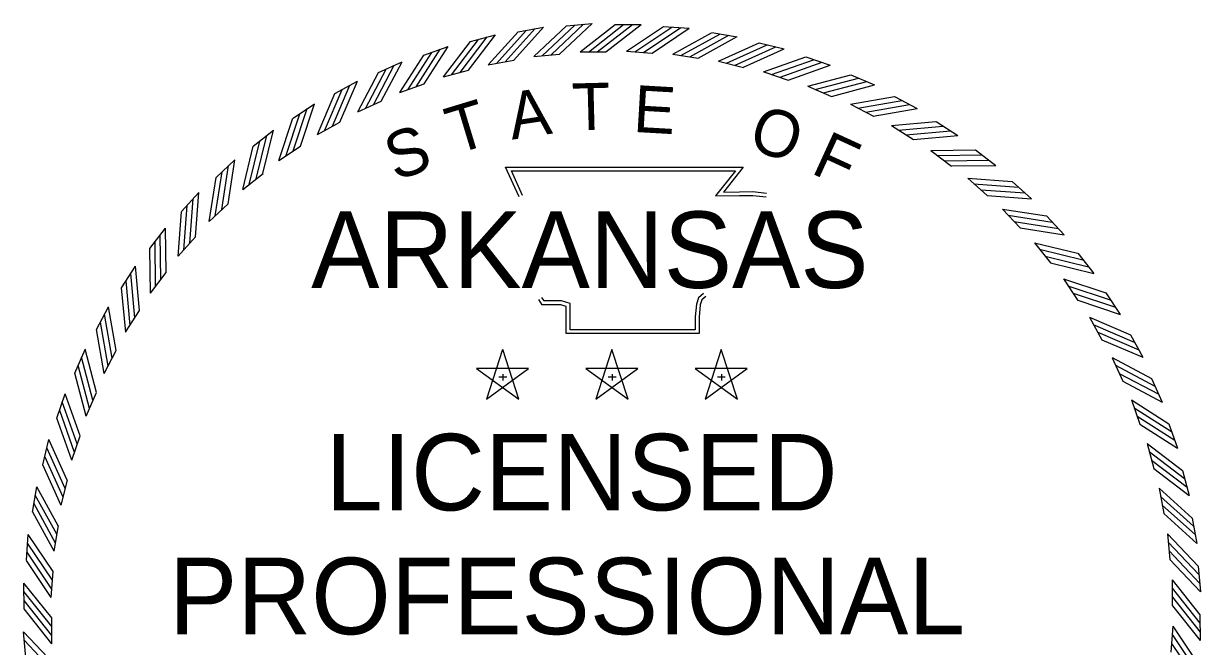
# Model space of a CAD drawing. Extents: x 1370130 to 1380143, y 377636 to 380256.
# Drawn here: x 1379550.7 to 1379757.3, y 377838.9 to 377948.2 of the extents above; entities that cross this region are included whole.
import ezdxf

# ---------------------------------------------------------------- set-up
doc = ezdxf.new("R2010")
doc.units = 0
doc.layers.add('STAMP_JUSTIN', color=7, linetype='Continuous')

msp = doc.modelspace()

# ---------------------------------------------------------------- linework, layer by layer
at = {"layer": 'STAMP_JUSTIN'}
for p, q in [((1379637.55, 377946.8), (1379642.01, 377947.59)), ((1379646.02, 377947.81), (1379650.53, 377948.23)), ((1379654.59, 377948.06), (1379659.11, 377948.06)), ((1379663.06, 377947.72), (1379667.57, 377947.39)), ((1379629.2, 377945.09), (1379633.57, 377946.24)), ((1379671.52, 377946.63), (1379675.99, 377945.92)), ((1379621.01, 377942.7), (1379625.28, 377944.21)), ((1379648.41, 377943.25), (1379652.95, 377943.25)), ((1379656.55, 377943.38), (1379661.07, 377943.04)), ((1379679.86, 377944.83), (1379684.25, 377943.76)), ((1379613.05, 377939.64), (1379617.18, 377941.5)), ((1379632.31, 377940.99), (1379636.78, 377941.77)), ((1379640.32, 377942.45), (1379644.83, 377942.87)), ((1379664.67, 377942.83), (1379669.15, 377942.13)), ((1379672.72, 377941.62), (1379677.12, 377940.54)), ((1379688.02, 377942.36), (1379692.31, 377940.93)), ((1379624.45, 377938.87), (1379628.84, 377940.02)), ((1379680.64, 377939.74), (1379684.94, 377938.31)), ((1379695.94, 377939.22), (1379700.1, 377937.44)), ((1379605.37, 377935.94), (1379609.33, 377938.13)), ((1379616.8, 377936.1), (1379621.07, 377937.62)), ((1379688.38, 377937.22), (1379692.54, 377935.44)), ((1379703.59, 377935.43), (1379707.58, 377933.32)), ((1379598.03, 377931.61), (1379601.79, 377934.12)), ((1379609.4, 377932.72), (1379613.53, 377934.58)), ((1379695.88, 377934.07), (1379699.89, 377931.95)), ((1379602.3, 377928.74), (1379606.27, 377930.93)), ((1379710.89, 377931.03), (1379714.7, 377928.59)), ((1379591.06, 377926.69), (1379594.6, 377929.5)), ((1379703.09, 377930.31), (1379706.91, 377927.86)), ((1379595.56, 377924.18), (1379599.33, 377926.69)), ((1379709.98, 377925.96), (1379713.58, 377923.21)), ((1379717.8, 377926.04), (1379721.4, 377923.3)), ((1379584.53, 377921.21), (1379587.83, 377924.3)), ((1379589.22, 377919.08), (1379592.77, 377921.9)), ((1379716.48, 377921.06), (1379719.84, 377918.02)), ((1379724.28, 377920.5), (1379727.64, 377917.46)), ((1379578.46, 377915.21), (1379581.5, 377918.57)), ((1379583.31, 377913.48), (1379586.62, 377916.58)), ((1379722.55, 377915.65), (1379725.65, 377912.34)), ((1379730.28, 377914.44), (1379733.38, 377911.14)), ((1379572.92, 377908.73), (1379575.67, 377912.33)), ((1379577.9, 377907.4), (1379580.94, 377910.77)), ((1379728.15, 377909.75), (1379730.97, 377906.19)), ((1379735.76, 377907.9), (1379738.57, 377904.36)), ((1379567.93, 377901.82), (1379570.37, 377905.63)), ((1379573, 377900.9), (1379575.75, 377904.51)), ((1379733.25, 377903.4), (1379735.77, 377899.63)), ((1379740.68, 377900.94), (1379743.19, 377897.17)), ((1379563.53, 377894.51), (1379565.64, 377898.51)), ((1379568.65, 377894.02), (1379571.1, 377897.84)), ((1379737.81, 377896.66), (1379740, 377892.69)), ((1379745.01, 377893.59), (1379747.2, 377889.63)), ((1379559.74, 377886.87), (1379561.52, 377891.03)), ((1379564.89, 377886.81), (1379567.01, 377890.81)), ((1379634.82, 377890.99), (1379631.99, 377882.3)), ((1379637.64, 377882.31), (1379634.83, 377891)), ((1379654.01, 377890.99), (1379651.18, 377882.3)), ((1379656.83, 377882.31), (1379654.01, 377891)), ((1379673.2, 377890.99), (1379670.37, 377882.3)), ((1379676.02, 377882.31), (1379673.2, 377891)), ((1379741.79, 377889.56), (1379743.65, 377885.43)), ((1379639.38, 377887.67), (1379630.25, 377887.68)), ((1379630.26, 377887.67), (1379637.64, 377882.3)), ((1379632, 377882.31), (1379639.39, 377887.67)), ((1379658.57, 377887.67), (1379649.44, 377887.68)), ((1379649.45, 377887.67), (1379656.83, 377882.3)), ((1379651.19, 377882.31), (1379658.58, 377887.67)), ((1379677.76, 377887.67), (1379668.63, 377887.68)), ((1379668.63, 377887.67), (1379676.02, 377882.3)), ((1379670.38, 377882.31), (1379677.77, 377887.67)), ((1379634.17, 377886.21), (1379635.53, 377886.21)), ((1379634.83, 377886.7), (1379634.83, 377885.55)), ((1379653.36, 377886.21), (1379654.72, 377886.21)), ((1379654.02, 377886.7), (1379654.02, 377885.55)), ((1379672.55, 377886.21), (1379673.9, 377886.21)), ((1379673.21, 377886.7), (1379673.21, 377885.55)), ((1379748.71, 377885.91), (1379750.57, 377881.78)), ((1379561.74, 377879.3), (1379563.52, 377883.47)), ((1379556.6, 377878.94), (1379558.03, 377883.24)), ((1379745.18, 377882.16), (1379746.69, 377877.89)), ((1379751.77, 377877.95), (1379753.28, 377873.68)), ((1379554.13, 377870.78), (1379555.2, 377875.18)), ((1379559.22, 377871.57), (1379560.65, 377875.87)), ((1379747.94, 377874.51), (1379749.09, 377870.12)), ((1379754.17, 377869.76), (1379755.32, 377865.39)), ((1379552.33, 377862.45), (1379553.04, 377866.91)), ((1379557.34, 377863.65), (1379558.42, 377868.05)), ((1379750.06, 377866.65), (1379750.85, 377862.19)), ((1379755.87, 377861.41), (1379756.66, 377856.95)), ((1379551.24, 377853.99), (1379551.57, 377858.5)), ((1379556.13, 377855.6), (1379556.84, 377860.08)), ((1379751.52, 377858.65), (1379751.94, 377854.13)), ((1379756.88, 377852.94), (1379757.3, 377848.44)), ((1379555.58, 377847.48), (1379555.92, 377852)), ((1379752.32, 377850.55), (1379752.36, 377846.01)), ((1379550.84, 377845.47), (1379550.8, 377849.99)), ((1379757.19, 377844.42), (1379757.23, 377839.89)), ((1379555.71, 377839.34), (1379555.67, 377843.88)), ((1379752.45, 377842.41), (1379752.12, 377837.89)), ((1379551.15, 377836.95), (1379550.73, 377841.45))]:
    msp.add_line(p, q, dxfattribs=at)
for points in [[(1379635.28, 377941.53), (1379640.53, 377947.34)], [(1379636.77, 377941.78), (1379642.01, 377947.59)], [(1379640.31, 377942.45), (1379646.02, 377947.81)], [(1379641.76, 377942.57), (1379647.47, 377947.93)], [(1379643.32, 377942.75), (1379649.03, 377948.11)], [(1379644.83, 377942.87), (1379650.53, 377948.23)], [(1379648.41, 377943.25), (1379654.58, 377948.06)], [(1379649.87, 377943.23), (1379656.04, 377948.05)], [(1379651.44, 377943.27), (1379657.61, 377948.08)], [(1379652.94, 377943.25), (1379659.12, 377948.07)], [(1379656.55, 377943.37), (1379663.06, 377947.72)], [(1379658, 377943.25), (1379664.51, 377947.6)], [(1379659.57, 377943.17), (1379666.08, 377947.52)], [(1379661.07, 377943.05), (1379667.58, 377947.4)], [(1379625.86, 377939.22), (1379630.61, 377945.44)], [(1379627.37, 377939.65), (1379632.12, 377945.88)], [(1379628.83, 377940.02), (1379633.58, 377946.25)], [(1379632.31, 377940.98), (1379637.55, 377946.79)], [(1379633.74, 377941.22), (1379638.98, 377947.03)], [(1379664.67, 377942.83), (1379671.51, 377946.62)], [(1379666.1, 377942.59), (1379672.95, 377946.38)], [(1379667.66, 377942.38), (1379674.51, 377946.17)], [(1379669.15, 377942.13), (1379675.99, 377945.93)], [(1379619.64, 377937.13), (1379623.86, 377943.72)], [(1379621.07, 377937.62), (1379625.28, 377944.21)], [(1379624.45, 377938.86), (1379629.19, 377945.09)], [(1379672.71, 377941.61), (1379679.85, 377944.83)], [(1379674.12, 377941.26), (1379681.26, 377944.47)], [(1379675.66, 377940.92), (1379682.79, 377944.14)], [(1379677.12, 377940.55), (1379684.26, 377943.77)], [(1379613.53, 377934.58), (1379617.18, 377941.5)], [(1379616.79, 377936.1), (1379621.01, 377942.69)], [(1379618.17, 377936.57), (1379622.39, 377943.17)], [(1379680.63, 377939.74), (1379688.01, 377942.36)], [(1379682.01, 377939.27), (1379689.39, 377941.88)], [(1379683.51, 377938.8), (1379690.89, 377941.42)], [(1379609.39, 377932.71), (1379613.05, 377939.64)], [(1379610.73, 377933.3), (1379614.38, 377940.22)], [(1379612.15, 377933.97), (1379615.8, 377940.9)], [(1379684.94, 377938.31), (1379692.31, 377940.93)], [(1379688.37, 377937.22), (1379695.94, 377939.22)], [(1379604.94, 377930.21), (1379608.01, 377937.41)], [(1379606.26, 377930.93), (1379609.33, 377938.13)], [(1379689.7, 377936.63), (1379697.27, 377938.63)], [(1379691.16, 377936.05), (1379698.73, 377938.05)], [(1379692.54, 377935.44), (1379700.11, 377937.44)], [(1379602.3, 377928.73), (1379605.37, 377935.93)], [(1379603.58, 377929.42), (1379606.65, 377936.62)], [(1379695.87, 377934.07), (1379703.58, 377935.43)], [(1379598.06, 377925.87), (1379600.53, 377933.3)], [(1379599.33, 377926.69), (1379601.79, 377934.12)], [(1379697.15, 377933.37), (1379704.86, 377934.74)], [(1379698.56, 377932.67), (1379706.26, 377934.04)], [(1379699.88, 377931.95), (1379707.59, 377933.32)], [(1379595.56, 377924.17), (1379598.02, 377931.6)], [(1379596.78, 377924.97), (1379599.24, 377932.4)], [(1379703.09, 377930.31), (1379710.88, 377931.03)], [(1379592.76, 377921.9), (1379594.61, 377929.5)], [(1379704.31, 377929.51), (1379712.1, 377930.24)], [(1379705.65, 377928.69), (1379713.44, 377929.42)], [(1379589.21, 377919.07), (1379591.06, 377926.68)], [(1379590.36, 377919.97), (1379592.21, 377927.58)], [(1379591.57, 377920.97), (1379593.42, 377928.58)], [(1379706.91, 377927.87), (1379714.7, 377928.59)], [(1379709.97, 377925.96), (1379717.8, 377926.04)], [(1379711.12, 377925.07), (1379718.95, 377925.15)], [(1379585.51, 377915.56), (1379586.72, 377923.29)], [(1379586.62, 377916.58), (1379587.83, 377924.31)], [(1379637.73, 377917.79), (1379635.32, 377923.01), (1379677.04, 377923.03), (1379673.56, 377918.65), (1379676.39, 377918.69), (1379678.76, 377918.72), (1379681.13, 377918.46)], [(1379712.39, 377924.14), (1379720.22, 377924.22)], [(1379713.58, 377923.22), (1379721.41, 377923.3)], [(1379583.31, 377913.47), (1379584.52, 377921.2)], [(1379584.38, 377914.46), (1379585.59, 377922.19)], [(1379638.33, 377918.06), (1379636.35, 377922.35), (1379675.67, 377922.37), (1379672.17, 377917.97), (1379676.4, 377918.03), (1379678.73, 377918.06), (1379681.05, 377917.81)], [(1379716.47, 377921.06), (1379724.28, 377920.5)], [(1379580.93, 377910.77), (1379581.5, 377918.57)], [(1379717.54, 377920.08), (1379725.35, 377919.51)], [(1379718.73, 377919.05), (1379726.54, 377918.48)], [(1379579.91, 377909.66), (1379580.48, 377917.46)], [(1379719.84, 377918.03), (1379727.65, 377917.46)], [(1379577.9, 377907.4), (1379578.46, 377915.2)], [(1379578.88, 377908.47), (1379579.45, 377916.27)], [(1379722.54, 377915.65), (1379730.28, 377914.44)], [(1379723.53, 377914.58), (1379731.26, 377913.37)], [(1379575.75, 377904.51), (1379575.67, 377912.33)], [(1379724.63, 377913.45), (1379732.36, 377912.24)], [(1379725.65, 377912.35), (1379733.38, 377911.14)], [(1379574.82, 377903.32), (1379574.74, 377911.14)], [(1379573, 377900.9), (1379572.92, 377908.72)], [(1379573.89, 377902.05), (1379573.81, 377909.87)], [(1379728.15, 377909.75), (1379735.75, 377907.9)], [(1379729.04, 377908.6), (1379736.65, 377906.75)], [(1379730.04, 377907.39), (1379737.65, 377905.54)], [(1379730.97, 377906.2), (1379738.58, 377904.36)], [(1379570.27, 377896.58), (1379569.54, 377904.37)], [(1379571.09, 377897.84), (1379570.37, 377905.63)], [(1379569.45, 377895.23), (1379568.73, 377903.03)], [(1379733.24, 377903.4), (1379740.67, 377900.94)], [(1379734.04, 377902.19), (1379741.47, 377899.72)], [(1379568.66, 377894.02), (1379567.93, 377901.81)], [(1379670.47, 377900.3), (1379669.76, 377899.72), (1379669.52, 377898.86), (1379669.29, 377896.69), (1379669.29, 377893.81), (1379646, 377893.81), (1379646, 377897.7), (1379646, 377898.57), (1379645.05, 377898.86), (1379641.74, 377898.86), (1379641.15, 377899.76)], [(1379670.05, 377900.81), (1379669.18, 377900.1), (1379668.87, 377898.98), (1379668.63, 377896.73), (1379668.63, 377894.47), (1379646.66, 377894.47), (1379646.66, 377897.7), (1379646.66, 377899.06), (1379645.15, 377899.52), (1379642.09, 377899.52), (1379641.7, 377900.12)], [(1379734.94, 377900.9), (1379742.37, 377898.43)], [(1379567.01, 377890.81), (1379565.64, 377898.52)], [(1379735.77, 377899.64), (1379743.19, 377897.17)], [(1379565.59, 377888.08), (1379564.22, 377895.79)], [(1379566.29, 377889.48), (1379564.93, 377897.19)], [(1379737.8, 377896.66), (1379745, 377893.59)], [(1379564.89, 377886.8), (1379563.53, 377894.51)], [(1379738.49, 377895.38), (1379745.69, 377892.31)], [(1379739.29, 377894.02), (1379746.49, 377890.95)], [(1379740, 377892.7), (1379747.2, 377889.63)], [(1379562.91, 377882.09), (1379560.91, 377889.66)], [(1379563.52, 377883.47), (1379561.52, 377891.04)], [(1379741.79, 377889.57), (1379748.71, 377885.91)], [(1379562.33, 377880.63), (1379560.33, 377888.2)], [(1379742.37, 377888.23), (1379749.29, 377884.58)], [(1379561.74, 377879.3), (1379559.74, 377886.86)], [(1379743.05, 377886.81), (1379749.97, 377883.16)], [(1379743.65, 377885.43), (1379750.57, 377881.78)], [(1379560.16, 377874.44), (1379557.54, 377881.82)], [(1379560.65, 377875.86), (1379558.03, 377883.24)], [(1379745.17, 377882.17), (1379751.77, 377877.95)], [(1379559.69, 377872.94), (1379557.08, 377880.31)], [(1379745.64, 377880.79), (1379752.24, 377876.58)], [(1379746.2, 377879.32), (1379752.8, 377875.11)], [(1379559.22, 377871.56), (1379556.6, 377878.94)], [(1379746.69, 377877.89), (1379753.29, 377873.68)], [(1379558.41, 377868.05), (1379555.2, 377875.18)], [(1379558.04, 377866.59), (1379554.83, 377873.72)], [(1379747.93, 377874.51), (1379754.16, 377869.77)], [(1379748.29, 377873.1), (1379754.52, 377868.36)], [(1379557.7, 377865.05), (1379554.49, 377872.19)], [(1379748.72, 377871.59), (1379754.95, 377866.84)], [(1379557.35, 377863.64), (1379554.13, 377870.78)], [(1379749.09, 377870.13), (1379755.32, 377865.38)], [(1379556.83, 377860.07), (1379553.04, 377866.92)], [(1379556.58, 377858.59), (1379552.79, 377865.43)], [(1379750.05, 377866.66), (1379755.87, 377861.41)], [(1379750.29, 377865.22), (1379756.11, 377859.98)], [(1379556.37, 377857.03), (1379552.58, 377863.88)], [(1379750.6, 377863.68), (1379756.41, 377858.44)], [(1379556.13, 377855.59), (1379552.34, 377862.44)], [(1379750.85, 377862.19), (1379756.66, 377856.95)], [(1379555.91, 377852), (1379551.57, 377858.51)], [(1379751.52, 377858.65), (1379756.88, 377852.95)], [(1379555.79, 377850.49), (1379551.44, 377857)], [(1379751.64, 377857.2), (1379757, 377851.49)], [(1379555.71, 377848.92), (1379551.36, 377855.43)], [(1379751.82, 377855.64), (1379757.18, 377849.93)], [(1379555.59, 377847.47), (1379551.24, 377853.98)], [(1379751.94, 377854.14), (1379757.3, 377848.43)], [(1379752.32, 377850.55), (1379757.19, 377844.42)], [(1379555.67, 377843.87), (1379550.8, 377850)], [(1379555.67, 377842.36), (1379550.8, 377848.49)], [(1379752.32, 377849.1), (1379757.19, 377842.97)], [(1379555.72, 377840.79), (1379550.85, 377846.92)], [(1379752.37, 377847.53), (1379757.24, 377841.4)], [(1379555.72, 377839.34), (1379550.85, 377845.46)], [(1379752.37, 377846.02), (1379757.24, 377839.89)], [(1379752.45, 377842.42), (1379756.79, 377835.91)], [(1379556.09, 377835.75), (1379550.73, 377841.46)], [(1379556.22, 377834.25), (1379550.86, 377839.96)], [(1379752.33, 377840.96), (1379756.67, 377834.46)], [(1379752.24, 377839.39), (1379756.59, 377832.89)]]:
    msp.add_lwpolyline(points, dxfattribs=at)

# ---------------------------------------------------------------- texts
for s, rotation, p in [('T', 1.4789, (1379647.09, 377929.47)), ('E', 356.672, (1379657.62, 377929.22)), ('T', 16.9015, (1379626.47, 377925.22)), ('A', 8.6788, (1379636.46, 377927.83)), ('O', 341.2218, (1379677.61, 377926.4)), ('S', 19.7726, (1379616, 377920.52)), ('F', 335.3628, (1379688.7, 377922.06))]:
    msp.add_text(s, height=8.23, rotation=rotation, dxfattribs=at).set_placement(p)
for s, height, p in [('ARKANSAS', 13.432, (1379601.22, 377901.8)), ('LICENSED', 13.432, (1379603.77, 377862.76)), ('PROFESSIONAL', 13.4323, (1379576.27, 377841.01))]:
    msp.add_text(s, height=height, dxfattribs=at).set_placement(p)

doc.saveas('drawing.dxf')
